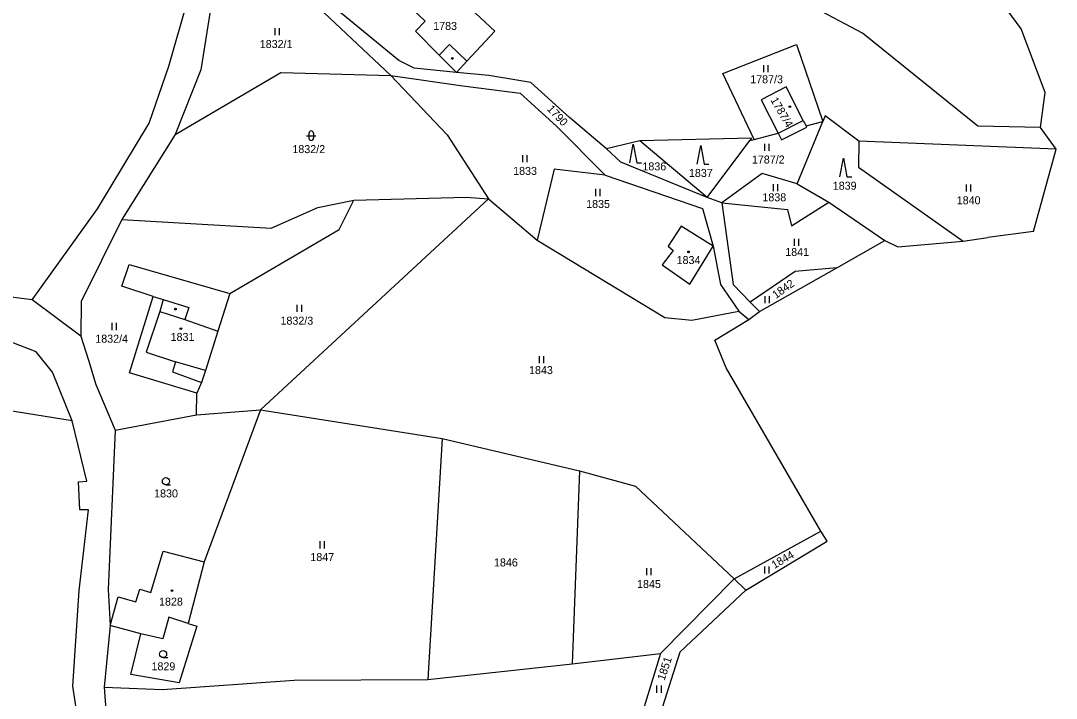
# Model space of a CAD drawing. Extents: x -670359 to -668019, y -978807 to -976674.
# Drawn here: x -668901.2 to -668681.2, y -978659.9 to -978516 of the extents above; entities that cross this region are included whole.
import ezdxf

# ---------------------------------------------------------------- set-up
doc = ezdxf.new("R2010")
doc.units = 0
for name, color, linetype in [('Hranice kat_území', 7, 'Continuous'), ('Hranice parcel', 7, 'Continuous'), ('Parcelní čísla', 7, 'Continuous'), ('Vnitřní kresba', 7, 'Continuous'), ('Značky budov', 7, 'Continuous'), ('Značky kultur', 7, 'Continuous')]:
    doc.layers.add(name, color=color, linetype=linetype)

msp = doc.modelspace()

# ---------------------------------------------------------------- linework, layer by layer
at = {"layer": 'Hranice kat_území'}
for points in [[(-668688.74, -978517.71), (-668698.82, -978503.85)], [(-668683.61, -978531.23), (-668688.74, -978517.71)], [(-668684.62, -978538.66), (-668683.61, -978531.23)], [(-668681.25, -978543.28), (-668684.62, -978538.66)], [(-668686.12, -978560.71), (-668681.25, -978543.28)], [(-668701.04, -978562.76), (-668695.79, -978562.04)], [(-668686.12, -978560.71), (-668695.79, -978562.04)], [(-668727.87, -978568.45), (-668717.69, -978562.63)], [(-668717.69, -978562.63), (-668714.91, -978563.96)], [(-668714.91, -978563.96), (-668701.04, -978562.76)], [(-668744.28, -978577.76), (-668727.87, -978568.45)], [(-668746.55, -978579.4), (-668744.28, -978577.76)], [(-668753.75, -978583.83), (-668746.55, -978579.4)], [(-668751.37, -978589.72), (-668753.75, -978583.83)], [(-668731.24, -978624.39), (-668751.37, -978589.72)], [(-668729.92, -978626.49), (-668731.24, -978624.39)], [(-668747.15, -978636.91), (-668729.92, -978626.49)], [(-668761.14, -978650.02), (-668747.15, -978636.91)], [(-668768.5, -978673.25), (-668761.14, -978650.02)]]:
    msp.add_lwpolyline(points, dxfattribs=at)
at = {"layer": 'Hranice parcel'}
for points in [[(-668820.84, -978524.42), (-668846.17, -978503.57)], [(-668869.69, -978525.63), (-668865.68, -978511.47)], [(-668860.65, -978512.19), (-668862.89, -978526.39)], [(-668839.1, -978512), (-668822.57, -978527.58)], [(-668819.55, -978512.04), (-668815.3, -978516.07)], [(-668800.48, -978518.18), (-668806.55, -978512.52)], [(-668722.37, -978518.63), (-668733.39, -978512.84)], [(-668815.3, -978516.07), (-668817.3, -978518.18)], [(-668817.3, -978518.18), (-668812.29, -978523.3)], [(-668806.43, -978524.55), (-668800.48, -978518.18)], [(-668697.9, -978538.34), (-668722.37, -978518.63)], [(-668752.04, -978527.16), (-668736.45, -978521.04)], [(-668736.45, -978521.04), (-668730.84, -978537.34)], [(-668817.59, -978526.07), (-668820.84, -978524.42)], [(-668808.63, -978526.95), (-668812.29, -978523.3)], [(-668806.43, -978524.55), (-668808.63, -978526.95)], [(-668873.9, -978537.72), (-668869.69, -978525.63)], [(-668862.89, -978526.39), (-668868.34, -978540.14)], [(-668868.34, -978540.14), (-668845.96, -978526.98)], [(-668845.96, -978526.98), (-668822.57, -978527.58)], [(-668808.63, -978526.95), (-668817.59, -978526.07)], [(-668801.77, -978527.63), (-668808.63, -978526.95)], [(-668745.4, -978541.17), (-668752.04, -978527.16)], [(-668822.57, -978527.58), (-668810.63, -978540.19)], [(-668822.57, -978527.58), (-668807.25, -978529.77)], [(-668792.83, -978529.07), (-668801.77, -978527.63)], [(-668784.63, -978536.49), (-668792.83, -978529.07)], [(-668807.25, -978529.77), (-668795.11, -978531.35)], [(-668795.11, -978531.35), (-668787.38, -978538.36)], [(-668738.6, -978530.03), (-668743.95, -978532.74)], [(-668734.97, -978537.14), (-668738.6, -978530.03)], [(-668743.95, -978532.74), (-668740.31, -978539.83)], [(-668884.86, -978555.92), (-668873.9, -978537.72)], [(-668776.74, -978543.19), (-668784.63, -978536.49)], [(-668736.29, -978550.62), (-668730.84, -978537.34)], [(-668734.97, -978537.14), (-668734.39, -978538.27)], [(-668734.39, -978538.27), (-668730.84, -978537.34)], [(-668730.36, -978536.17), (-668730.84, -978537.34)], [(-668723.17, -978541.58), (-668730.36, -978536.17)], [(-668868.34, -978540.14), (-668879.69, -978558.18)], [(-668810.63, -978540.19), (-668801.82, -978553.79)], [(-668787.38, -978538.36), (-668777.08, -978548.79)], [(-668745.4, -978541.17), (-668740.31, -978539.83)], [(-668740.31, -978539.83), (-668739.59, -978541.25)], [(-668739.59, -978541.25), (-668734.24, -978538.56)], [(-668734.24, -978538.56), (-668734.39, -978538.27)], [(-668684.62, -978538.66), (-668697.9, -978538.34)], [(-668769.67, -978541.48), (-668776.74, -978543.19)], [(-668745.97, -978540.93), (-668769.67, -978541.48)], [(-668755.39, -978553.49), (-668769.67, -978541.48)], [(-668755.39, -978553.49), (-668746.33, -978541.42)], [(-668745.97, -978540.93), (-668746.33, -978541.42)], [(-668746.33, -978541.42), (-668745.4, -978541.17)], [(-668723.17, -978541.58), (-668723.26, -978547.09)], [(-668681.25, -978543.28), (-668723.17, -978541.58)], [(-668773.75, -978546.04), (-668776.74, -978543.19)], [(-668755.39, -978553.49), (-668773.75, -978546.04)], [(-668787.86, -978547.48), (-668791.48, -978562.61)], [(-668777.08, -978548.79), (-668787.86, -978547.48)], [(-668777.08, -978548.79), (-668756.39, -978555.87)], [(-668743.69, -978548.41), (-668752.29, -978554.66)], [(-668736.29, -978550.62), (-668743.69, -978548.41)], [(-668723.26, -978547.09), (-668701.04, -978562.76)], [(-668736.29, -978550.62), (-668729.55, -978554.5)], [(-668830.43, -978554.09), (-668806.58, -978553.48)], [(-668806.58, -978553.48), (-668801.82, -978553.79)], [(-668752.29, -978554.66), (-668755.39, -978553.49)], [(-668850.22, -978598.65), (-668801.82, -978553.79)], [(-668848.01, -978560.04), (-668838.1, -978555.63)], [(-668838.1, -978555.63), (-668830.43, -978554.09)], [(-668833.55, -978560.28), (-668830.43, -978554.09)], [(-668801.82, -978553.79), (-668791.48, -978562.61)], [(-668752.29, -978554.66), (-668749.87, -978571.98)], [(-668752.29, -978554.66), (-668738.3, -978556.03)], [(-668737.48, -978559.56), (-668729.55, -978554.5)], [(-668729.55, -978554.5), (-668717.69, -978562.63)], [(-668898.72, -978575.28), (-668884.86, -978555.92)], [(-668756.39, -978555.87), (-668754.13, -978563.83)], [(-668738.3, -978556.03), (-668737.48, -978559.56)], [(-668879.69, -978558.18), (-668888.32, -978575.62)], [(-668879.69, -978558.18), (-668848.01, -978560.04)], [(-668760.94, -978559.63), (-668763.65, -978563.82)], [(-668754.13, -978563.83), (-668760.94, -978559.63)], [(-668856.77, -978573.88), (-668833.55, -978560.28)], [(-668791.48, -978562.61), (-668764.39, -978579.01)], [(-668763.65, -978563.82), (-668762.63, -978564.8)], [(-668759.07, -978571.9), (-668754.13, -978563.83)], [(-668754.13, -978563.83), (-668752.59, -978572.02)], [(-668762.63, -978564.8), (-668764.92, -978567.8)], [(-668879.67, -978572.36), (-668878.16, -978567.75)], [(-668878.16, -978567.75), (-668856.77, -978573.88)], [(-668764.92, -978567.8), (-668759.07, -978571.9)], [(-668727.87, -978568.45), (-668736.69, -978569.26)], [(-668736.69, -978569.26), (-668746.25, -978575.73)], [(-668873.01, -978574.53), (-668879.67, -978572.36)], [(-668752.59, -978572.02), (-668748.68, -978577.68)], [(-668749.87, -978571.98), (-668746.25, -978575.73)], [(-668898.72, -978575.28), (-668911.1, -978573.7)], [(-668888.37, -978582.98), (-668898.72, -978575.28)], [(-668878.09, -978590.76), (-668873.01, -978574.53)], [(-668856.77, -978573.88), (-668859.29, -978581.89)], [(-668888.32, -978575.62), (-668888.37, -978582.98)], [(-668758.64, -978579.59), (-668748.68, -978577.68)], [(-668748.68, -978577.68), (-668746.55, -978579.4)], [(-668746.25, -978575.73), (-668744.28, -978577.76)], [(-668764.39, -978579.01), (-668758.64, -978579.59)], [(-668859.29, -978581.89), (-668861.92, -978590.25)], [(-668897.87, -978586.33), (-668903.91, -978583.99)], [(-668888.37, -978582.98), (-668886.77, -978588.05)], [(-668894.42, -978590.63), (-668897.87, -978586.33)], [(-668886.77, -978588.05), (-668885.18, -978593.2)], [(-668890.24, -978600.95), (-668894.42, -978590.63)], [(-668863.76, -978595.09), (-668878.09, -978590.76)], [(-668861.92, -978590.25), (-668862.76, -978592.79)], [(-668862.76, -978592.79), (-668863.76, -978595.09)], [(-668885.18, -978593.2), (-668881.11, -978602.95)], [(-668863.84, -978599.65), (-668863.76, -978595.09)], [(-668890.24, -978600.95), (-668903.93, -978598.79)], [(-668881.11, -978602.95), (-668863.84, -978599.65)], [(-668863.84, -978599.65), (-668850.22, -978598.65)], [(-668850.22, -978598.65), (-668862.22, -978630.88)], [(-668850.22, -978598.65), (-668811.66, -978604.73)], [(-668887.14, -978613.8), (-668890.24, -978600.95)], [(-668881.11, -978602.95), (-668882.57, -978636.76)], [(-668811.66, -978604.73), (-668814.71, -978655.87)], [(-668811.66, -978604.73), (-668782.49, -978611.57)], [(-668782.49, -978611.57), (-668784.08, -978652.57)], [(-668782.49, -978611.57), (-668770.62, -978614.81)], [(-668888.9, -978613.93), (-668887.14, -978613.8)], [(-668888.6, -978619.85), (-668888.9, -978613.93)], [(-668770.62, -978614.81), (-668749.69, -978634.51)], [(-668888.74, -978636.97), (-668886.76, -978619.89)], [(-668886.76, -978619.89), (-668888.6, -978619.85)], [(-668749.69, -978634.51), (-668731.24, -978624.39)], [(-668873.54, -978637.4), (-668870.91, -978628.61)], [(-668870.91, -978628.61), (-668862.22, -978630.88)], [(-668862.22, -978630.88), (-668865.57, -978644.02)], [(-668749.69, -978634.51), (-668765.31, -978650.35)], [(-668749.69, -978634.51), (-668747.15, -978636.91)], [(-668890.13, -978657.34), (-668888.74, -978636.97)], [(-668882.57, -978636.76), (-668882.14, -978644.45)], [(-668876.69, -978639.38), (-668875.89, -978636.68)], [(-668875.89, -978636.68), (-668873.54, -978637.4)], [(-668882.14, -978644.45), (-668880.44, -978638.32)], [(-668880.44, -978638.32), (-668876.69, -978639.38)], [(-668869.71, -978642.67), (-668870.99, -978647.28)], [(-668865.57, -978644.02), (-668869.71, -978642.67)], [(-668882.14, -978644.45), (-668883.41, -978657.54)], [(-668875.69, -978646.16), (-668882.14, -978644.45)], [(-668863.74, -978644.53), (-668867.55, -978656.62)], [(-668865.57, -978644.02), (-668863.74, -978644.53)], [(-668877.76, -978654.84), (-668875.69, -978646.16)], [(-668870.99, -978647.28), (-668875.69, -978646.16)], [(-668784.08, -978652.57), (-668765.31, -978650.35)], [(-668765.31, -978650.35), (-668774.13, -978679.23)], [(-668814.71, -978655.87), (-668784.08, -978652.57)], [(-668867.55, -978656.62), (-668877.76, -978654.84)], [(-668871.09, -978658), (-668843.12, -978656.01)], [(-668843.12, -978656.01), (-668814.71, -978655.87)], [(-668889.34, -978662.4), (-668890.13, -978657.34)], [(-668883.41, -978657.54), (-668882.13, -978675.88)], [(-668883.41, -978657.54), (-668871.09, -978658)]]:
    msp.add_lwpolyline(points, dxfattribs=at)
at = {"layer": 'Vnitřní kresba'}
for points in [[(-668812.29, -978523.3), (-668810.08, -978521.02), (-668806.43, -978524.55)], [(-668740.31, -978539.83), (-668734.97, -978537.14)], [(-668873.01, -978574.53), (-668870.94, -978575.21)], [(-668870.94, -978575.21), (-668871.63, -978577.76)], [(-668870.94, -978575.21), (-668865.45, -978576.87)], [(-668871.63, -978577.76), (-668874.5, -978586.35)], [(-668871.63, -978577.76), (-668866.33, -978579.45)], [(-668865.45, -978576.87), (-668866.33, -978579.45)], [(-668866.33, -978579.45), (-668859.29, -978581.89)], [(-668874.5, -978586.35), (-668868.29, -978588.45)], [(-668868.29, -978588.45), (-668868.93, -978590.56)], [(-668861.92, -978590.25), (-668868.29, -978588.45)], [(-668868.93, -978590.56), (-668862.76, -978592.79)]]:
    msp.add_lwpolyline(points, dxfattribs=at)
at = {"layer": 'Značky budov'}
for centre in [(-668737.82, -978534.21), (-668759.34, -978565.06), (-668867.15, -978581.38), (-668869.05, -978637)]:
    msp.add_circle(centre, 0.175, dxfattribs=at)
at = {"layer": 'Značky kultur'}
for p, q in [((-668847.22, -978517.57), (-668847.22, -978519.07)), ((-668846.22, -978519.07), (-668846.22, -978517.57)), ((-668743.41, -978525.42), (-668743.41, -978526.92)), ((-668742.41, -978526.92), (-668742.41, -978525.42)), ((-668839.97, -978539.89), (-668839.97, -978540.89)), ((-668838.97, -978539.89), (-668838.97, -978540.89)), ((-668840.47, -978540.39), (-668838.47, -978540.39)), ((-668743.2, -978542.09), (-668743.2, -978543.59)), ((-668742.2, -978543.59), (-668742.2, -978542.09)), ((-668794.59, -978544.52), (-668794.59, -978546.02)), ((-668793.59, -978546.02), (-668793.59, -978544.52)), ((-668741.4, -978550.7), (-668741.4, -978552.2)), ((-668740.4, -978552.2), (-668740.4, -978550.7)), ((-668700.39, -978550.76), (-668700.39, -978552.26)), ((-668699.39, -978552.26), (-668699.39, -978550.76)), ((-668779.09, -978551.71), (-668779.09, -978553.21)), ((-668778.09, -978553.21), (-668778.09, -978551.71)), ((-668736.93, -978562.26), (-668736.93, -978563.76)), ((-668735.93, -978563.76), (-668735.93, -978562.26)), ((-668743.14, -978574.48), (-668743.14, -978575.98)), ((-668742.14, -978575.98), (-668742.14, -978574.48)), ((-668842.5, -978576.33), (-668842.5, -978577.83)), ((-668841.5, -978577.83), (-668841.5, -978576.33)), ((-668881.79, -978580.16), (-668881.79, -978581.66)), ((-668880.79, -978581.66), (-668880.79, -978580.16)), ((-668791.04, -978587.19), (-668791.04, -978588.69)), ((-668790.04, -978588.69), (-668790.04, -978587.19)), ((-668870.33, -978614.52), (-668869.33, -978614.52)), ((-668837.66, -978626.54), (-668837.66, -978628.04)), ((-668836.66, -978628.04), (-668836.66, -978626.54)), ((-668768.28, -978632.26), (-668768.28, -978633.76)), ((-668767.28, -978633.76), (-668767.28, -978632.26)), ((-668743.23, -978631.89), (-668743.23, -978633.39)), ((-668742.23, -978633.39), (-668742.23, -978631.89)), ((-668870.93, -978651.25), (-668869.93, -978651.25)), ((-668766.12, -978657.2), (-668766.12, -978658.7)), ((-668765.12, -978658.7), (-668765.12, -978657.2))]:
    msp.add_line(p, q, dxfattribs=at)
for points in [[(-668771.82, -978546.16), (-668771.07, -978542.16), (-668770.32, -978546.16), (-668769.32, -978546.16)], [(-668757.51, -978546.45), (-668756.76, -978542.45), (-668756.01, -978546.45), (-668755.01, -978546.45)], [(-668727.2, -978549.16), (-668726.45, -978545.16), (-668725.7, -978549.16), (-668724.7, -978549.16)]]:
    msp.add_lwpolyline(points, dxfattribs=at)
for centre, radius in [((-668809.52, -978523.99), 0.175), ((-668737.82, -978534.21), 0.175), ((-668759.34, -978565.06), 0.175), ((-668868.3, -978577.23), 0.175), ((-668867.15, -978581.38), 0.175), ((-668870.33, -978613.77), 0.75), ((-668869.05, -978637), 0.175), ((-668870.93, -978650.5), 0.75)]:
    msp.add_circle(centre, radius, dxfattribs=at)
for centre, start, end in [((-668839.47, -978539.89), 0, 180), ((-668839.47, -978540.89), 180, 0)]:
    msp.add_arc(centre, 0.5, start, end, dxfattribs=at)

# ---------------------------------------------------------------- texts
at = {"layer": 'Parcelní čísla'}
for s, p in [('1783', (-668813.57, -978517.93)), ('1832/1', (-668850.4, -978521.77)), ('1787/3', (-668746.25, -978529.26)), ('1832/2', (-668843.47, -978544.09)), ('1787/2', (-668745.89, -978546.3)), ('1836', (-668769.14, -978547.76)), ('1833', (-668796.59, -978548.72)), ('1837', (-668759.26, -978549.15)), ('1839', (-668728.72, -978551.86)), ('1838', (-668743.66, -978554.32)), ('1840', (-668702.39, -978554.96)), ('1835', (-668781.09, -978555.74)), ('1841', (-668738.81, -978565.94)), ('1834', (-668761.88, -978567.66)), ('1832/3', (-668846, -978580.53)), ('1832/4', (-668885.33, -978584.36)), ('1831', (-668869.33, -978583.98)), ('1843', (-668793.22, -978591.03)), ('1830', (-668872.83, -978617.22)), ('1847', (-668839.66, -978630.74)), ('1846', (-668800.66, -978631.88)), ('1845', (-668770.28, -978636.46)), ('1828', (-668871.79, -978640.2)), ('1829', (-668873.39, -978653.95))]:
    msp.add_text(s, height=1.7, dxfattribs=at).set_placement(p)
for s, rotation, p in [('1787/4', 300.0686, (-668742, -978532.81)), ('1790', 313.2851, (-668789.52, -978534.83)), ('1842', 35.5844, (-668740.8, -978575.1)), ('1844', 30.2726, (-668741.12, -978632.44)), ('1851', 71.7072, (-668764.44, -978656.22))]:
    msp.add_text(s, height=1.7, rotation=rotation, dxfattribs=at).set_placement(p)

doc.saveas('drawing.dxf')
